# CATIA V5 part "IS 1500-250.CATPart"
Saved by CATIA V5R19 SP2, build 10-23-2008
Part number: IS 1500-250
Bounding box of the stored display mesh (mm): x -37.351 to 37.351, y -37.351 to 37.351, z 0 to 610
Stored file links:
  C:\Users\Bora\Desktop\3D Katı model\IS serisi\IS 1500\IS 1500-250.CATPart
  C:\Program Files\Dassault Systemes\B19\intel_a\reffiles\standard\MetricThickPitch.txt
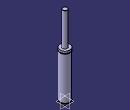
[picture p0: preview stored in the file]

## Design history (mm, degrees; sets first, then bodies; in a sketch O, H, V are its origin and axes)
Body1 (main body)
  Sketch1 on yz-plane, origin (0, 0, 0), H (0, 1, 0), V (0, 0, 1)
    point P1 (37.5, 341.5)
    point P4 (37.5, 336.5)
    point P7 (18, 609)
    point P9 (18, 609)
    point P13 (37.5, 341.5)
    point P14 (37.5, 336.5)
    line L1 (37.5, 341.5) -> (37.5, 357)
    line L2 (37.5, 13) -> (37.5, 336.5)
    line L3 (33.5, 13) -> (33.5, 8)
    arc A1 centre (17, 609) radius 1 from (18, 609) to (17, 610) ccw
    line L4 (18, 609) -> (18, 357)
    line L5 (37.5, 0) -> (37.5, 8)
    arc A2 centre (37.5, 339) radius 2.5 from (37.5, 341.5) to (37.5, 336.5) ccw
    line L6 (17, 610) -> (0, 610)
    point P15 (0, 610)
    line L7 (18, 357) -> (37.5, 357)
    line L8 (0, 0) -> (37.5, 0)
    line L9 (33.5, 13) -> (37.5, 13)
    line L10 (33.5, 8) -> (37.5, 8)
    coincidence: P15 V, P1 P13, P4 P14, P7 P9
    tangency: L6 A1
    horizontal: L7 H, L8 H, L9 H, L10 H
  Shaft1: profile Sketch1, axis Sketch1.V, angle 360
  Sketch2 on face of Shaft1 from Sketch1.L8, origin (0, 0, 0), H (1, 0, 0), V (0, -1, 0)
    point P1 (20, 0)
    distance P1 V = 20
  Hole1: placed by Sketch2, at (20, 0, 0) direction (0, 0, 1), diameter 6.647, depth 13, threaded "M8", thread diameter 8, thread depth 13, pitch 1.25
  CircPattern1: of Hole1, instances 4, angular step 90, axis from xy-plane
